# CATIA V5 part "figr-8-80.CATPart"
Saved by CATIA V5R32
Part number: Part1
Bounding box of the stored display mesh (mm): x -52.625 to 52.625, y -77.625 to 77.625, z 0 to 30
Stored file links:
  D:\PROJECTS\Project 2022\CATIA V5 6R 2022\Resources\Part Files\c08_catia_v5_6r2022_prt\figr-8-80.CATPart
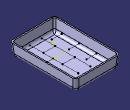
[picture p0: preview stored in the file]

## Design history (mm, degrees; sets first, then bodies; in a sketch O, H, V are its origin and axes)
Set1
  Plane1: type Offset, RefPlane xy-plane, Offset 30
  Plane2: type Offset, RefPlane face of Pad1, Offset -8, reversed
Body1 (main body)
  Sketch1 on xy-plane, origin (0, 0, 0), H (1, 0, 0), V (0, 1, 0)
    line L1 (-50, 75) -> (50, 75)
    line L2 (50, 75) -> (50, -75)
    line L3 (50, -75) -> (-50, -75)
    line L4 (-50, -75) -> (-50, 75)
    axis line L5 (50, -75) -> (-50, 75)
    length L3 = 100
    length L2 = 150
    horizontal: L1 H, L3 H
    vertical: L2 V, L4 V
    midpoint: O L5
  Pad1: profile Sketch1, direction (0, 0, 1), length 0, opposite side up to Plane1
  Draft1: Angle -5, Neutral face of Pad1, PullDir face of Pad1, SupportToDraft (face of Pad1; face of Pad1; face of Pad1; face of Pad1)
  Fillet1: radius 7, on edge [face of Pad1 | face of Pad1] (x4)
  Fillet2: radius 10, on edge [face of Pad1 | face of Pad1] (x4)
  Shell1: ExtOffset 0, Face face of Pad1, IntOffset 3
  Sketch2 on Plane2, origin (0, 0, 22), H (1, 0, 0), V (0, -1, 0)
    line L1 (28.1747, 54.0191) -> (28.1747, -59.2866)
    line L2 (0, 54.0191) -> (0, -59.2866)
    point P3 (0, 54.0191)
    line L3 (-9.5939, 0) -> (-33.0562, 0)
    point P5 (-9.5939, 0)
    line L4 (-9.5939, -40.4023) -> (-33.0562, -40.4023)
    point P7 (-9.5939, -40.4023)
    point P8 (-33.0562, -40.4023)
    point P9 (-33.0562, 40.4023)
    point P10 (-9.5939, 40.4023)
    line L5 (-9.5939, 40.4023) -> (-33.0562, 40.4023)
    line L6 (28.1747, 22.6983) -> (0, 22.6983)
    point P11 (28.1747, 22.6983)
    point P12 (0, 22.6983)
    point P13 (0, -22.6983)
    point P14 (28.1747, -22.6983)
    line L7 (28.1747, -22.6983) -> (0, -22.6983)
    line L8 (28.1747, 0) -> (41.8849, 0)
    point P15 (28.1747, 0)
    vertical: L1 V, L2 V
    coincidence: P3 V, P5 H, P11 L1, P12 L2, P15 L1, P15 H
    horizontal: L3 H, L4 H, L6 H, L8 H
    symmetry: P8 P9 L3, P7 P10 L3, L4 L5 L3, P12 P13 H, P11 P14 H, L6 L7 H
